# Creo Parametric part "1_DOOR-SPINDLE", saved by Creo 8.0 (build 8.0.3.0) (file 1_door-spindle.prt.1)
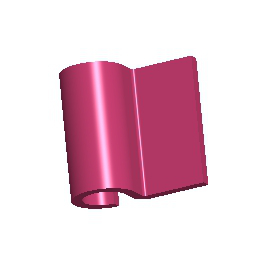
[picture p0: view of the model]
Units: millimeter Newton Second (mmNs); MM, TONNE, SECS

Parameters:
  SMT_DFLT_BEND_REL_LENGTH_TYPE = "Through All"

Other parameters: SMT_UPDATE_BEND_ALLOW_INFO, SMT_THICKNESS, SMT_PART_BEND_ALLOWANCE_FACTOR, SMT_DFLT_BEND_RADIUS, SMT_DFLT_BEND_ANGLE, SMT_DFLT_CRNR_REL_WIDTH, SMT_DFLT_CRNR_REL_DEPTH, SMT_DFLT_BEND_REL_WIDTH, SMT_DFLT_BEND_REL_DEPTH, SMT_DFLT_BEND_REL_LENGTH, SMT_DFLT_BEND_REL_ANGLE, SMT_GAP, SMT_DFLT_EDGE_TREA_WIDTH, SMT_DFLT_MITER_CUT_WIDTH, SMT_DFLT_MITER_CUT_OFFSET

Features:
  1. datum plane "RIGHT"
  2. datum plane "TOP"
  3. datum plane "FRONT"
  4. coordinate system

Layers: 1, 0_ALL_AXIS, 0_ALL_CSYS, 0_ALL_CURVES, 0_ALL_PLANES, 0_ALL_POINTS, 0_ALL_SURFS

Surfaces: 14 plane, 4 cylinder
